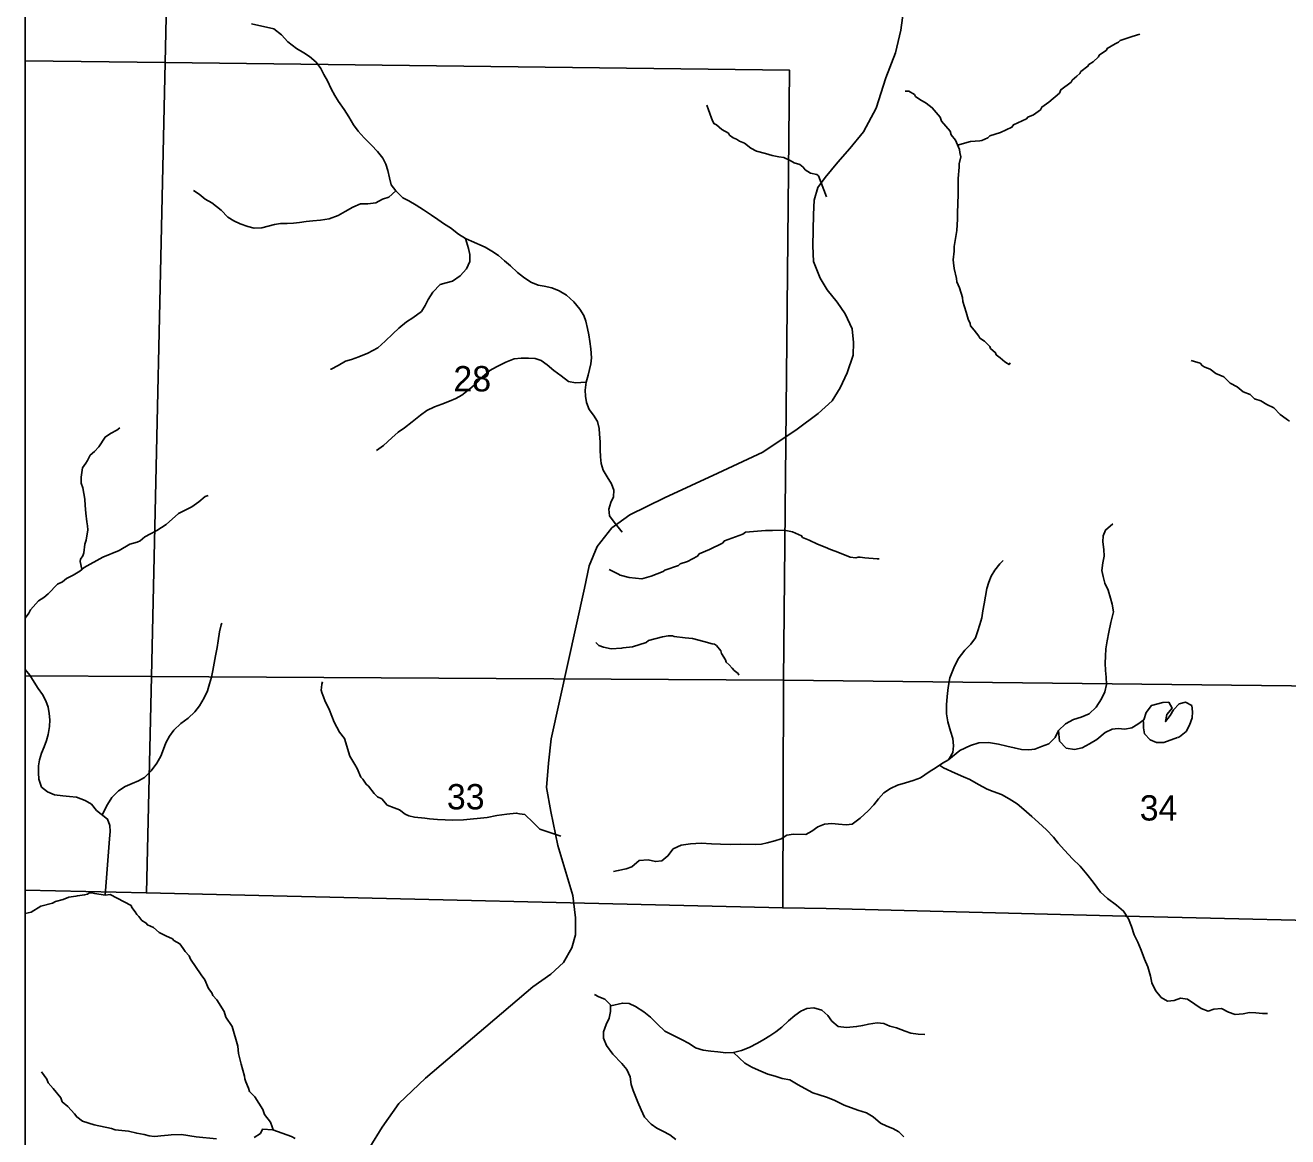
# Model space of a CAD drawing. Extents: x -10 to 158, y 8 to 33.
# Drawn here: x 2.1 to 4.186, y 15.67 to 17.507 of the extents above; entities that cross this region are included whole.
import ezdxf

# ---------------------------------------------------------------- set-up
doc = ezdxf.new("R2010")
doc.units = 0
for name, color, linetype in [('GM_X_Corporation', 7, 'Continuous'), ('GM_X_Minor_River', 7, 'Continuous'), ('GM_X_Rail_Line', 7, 'Continuous'), ('GM_X_Section_Text', 7, 'Continuous')]:
    doc.layers.add(name, color=color, linetype=linetype)

msp = doc.modelspace()

# ---------------------------------------------------------------- linework, layer by layer
at = {"layer": 'GM_X_Corporation'}
msp.add_lwpolyline([(5.7441, 17.4016), (5.3204, 17.3974), (4.9935, 17.4026), (4.6584, 17.4086), (4.4004, 17.4134), (4.4034, 17.9704), (4.4042, 18.3894), (4.0024, 18.3977), (3.4726, 18.3965), (3.3689, 18.3974), (3.3767, 18.6789), (3.3859, 18.705), (3.3893, 18.7211), (3.3872, 18.7823), (3.3779, 18.9242), (3.3711, 18.9532), (3.3709, 19.4089), (3.3147, 19.4093), (2.7824, 19.4152), (2.1, 19.4241), (2.1, 14.1), (8.9, 14.1)], dxfattribs=at)
for points in [[(2.1, 18.4216), (2.1, 17.4478), (2.3314, 17.4451), (2.3525, 18.417)], [(2.1, 17.4478), (2.1, 16.4315), (2.3088, 16.4308), (2.3314, 17.4451)], [(2.3314, 17.4451), (3.3626, 17.4323), (3.3525, 16.4245), (2.3088, 16.4308)], [(2.1, 16.4315), (2.1, 16.0777), (2.3002, 16.073), (2.3088, 16.4308)], [(2.3088, 16.4308), (3.3525, 16.4245), (3.3513, 16.0482), (2.4158, 16.0705), (2.3002, 16.073)], [(3.3525, 16.4245), (4.3887, 16.4129), (4.3853, 16.0237), (3.9176, 16.0345), (3.4233, 16.047), (3.3513, 16.0482)]]:
    msp.add_lwpolyline(points, close=True, dxfattribs=at)
at = {"layer": 'GM_X_Minor_River'}
for points in [[(3.086, 16.6691), (3.0729, 16.6858), (3.0649, 16.6963), (3.0641, 16.707), (3.0672, 16.7179), (3.0717, 16.7276), (3.0721, 16.7383), (3.0683, 16.749), (3.0614, 16.7607), (3.0546, 16.7716), (3.0512, 16.7827), (3.0501, 16.7938), (3.0497, 16.8052), (3.0498, 16.8181), (3.0487, 16.831), (3.0479, 16.8406), (3.0456, 16.8517), (3.0388, 16.8622), (3.0315, 16.8719), (3.0274, 16.8831), (3.0254, 16.8938), (3.0247, 16.9037), (3.0266, 16.9169), (3.0297, 16.9286), (3.0342, 16.9474), (3.0353, 16.9573), (3.0346, 16.9721), (3.0328, 16.984), (3.0309, 16.995), (3.029, 17.0058), (3.026, 17.0176), (3.0225, 17.0273), (3.0164, 17.0374), (3.0062, 17.0499), (2.994, 17.0606), (2.9818, 17.0678), (2.9698, 17.0728), (2.9573, 17.0755), (2.9471, 17.0774), (2.9351, 17.082), (2.9233, 17.0904), (2.9133, 17.0984), (2.9015, 17.1094), (2.8919, 17.1174), (2.8816, 17.1265), (2.8708, 17.1337), (2.8597, 17.1402), (2.8372, 17.1501), (2.8275, 17.1546), (2.8156, 17.1615), (2.8026, 17.1718), (2.7926, 17.1782), (2.7818, 17.1858), (2.7711, 17.1927), (2.7577, 17.2015), (2.7458, 17.2092), (2.7335, 17.2164), (2.7238, 17.2217), (2.7121, 17.2332), (2.7044, 17.2433), (2.7018, 17.2544), (2.6992, 17.267), (2.6957, 17.2774), (2.6908, 17.2871), (2.682, 17.2984), (2.6718, 17.3087), (2.66, 17.3209), (2.6498, 17.3319), (2.6421, 17.342), (2.6343, 17.3556), (2.6267, 17.3673), (2.6173, 17.3809), (2.6115, 17.3906), (2.6055, 17.4018), (2.5991, 17.415), (2.5934, 17.4254), (2.5884, 17.4355), (2.5808, 17.4456), (2.5697, 17.4551), (2.5601, 17.4612), (2.5482, 17.4684), (2.5337, 17.4796), (2.5231, 17.491), (2.5109, 17.5009), (2.4736, 17.5094)], [(3.6402, 17.3087), (3.6616, 17.3149), (3.6772, 17.3159), (3.6802, 17.3163), (3.6904, 17.321), (3.6933, 17.3241), (3.7111, 17.3297), (3.7299, 17.3384), (3.7325, 17.3422), (3.754, 17.3521), (3.7562, 17.3548), (3.7656, 17.3587), (3.7769, 17.3672), (3.7791, 17.3715), (3.7911, 17.3796), (3.8083, 17.3947), (3.8109, 17.4001), (3.8277, 17.4125), (3.8296, 17.4159), (3.837, 17.4229), (3.8419, 17.4272), (3.8437, 17.4302), (3.8554, 17.4391), (3.8568, 17.4418), (3.864, 17.4465), (3.8729, 17.4546), (3.874, 17.4573), (3.886, 17.4655), (3.8875, 17.4685), (3.9006, 17.4763), (3.9059, 17.4791), (3.9089, 17.4814), (3.9285, 17.4882), (3.9414, 17.4922)], [(3.5538, 17.398), (3.5596, 17.3979), (3.5692, 17.3921), (3.5704, 17.3891), (3.5777, 17.3839), (3.5884, 17.3779), (3.5984, 17.3705), (3.6112, 17.3551), (3.6136, 17.348), (3.6279, 17.3315), (3.6295, 17.3258), (3.6369, 17.3168), (3.6433, 17.3013), (3.6437, 17.2964), (3.6454, 17.2896), (3.6429, 17.2778), (3.643, 17.2724), (3.641, 17.2534), (3.6412, 17.2439), (3.6411, 17.2272), (3.6401, 17.1968), (3.6403, 17.1861), (3.6387, 17.1675), (3.6346, 17.1412), (3.6344, 17.1336), (3.6331, 17.1192), (3.6332, 17.1139), (3.6345, 17.1048), (3.6386, 17.0885), (3.6391, 17.0828), (3.6434, 17.073), (3.6482, 17.0571), (3.6491, 17.0503), (3.6544, 17.0329), (3.6576, 17.0212), (3.6608, 17.014), (3.6616, 17.0098), (3.6674, 17.0031), (3.6755, 16.9929), (3.6771, 16.9899), (3.6848, 16.9847), (3.6933, 16.9758), (3.6945, 16.9727), (3.703, 16.9656), (3.7038, 16.9622), (3.7107, 16.957), (3.7184, 16.9507), (3.7226, 16.9477), (3.7253, 16.9459), (3.7268, 16.9489)], [(3.4235, 17.2232), (3.4105, 17.2578), (3.4078, 17.26), (3.3972, 17.2621), (3.3926, 17.2651), (3.3883, 17.268), (3.3849, 17.2722), (3.3795, 17.2766), (3.3703, 17.2795), (3.3634, 17.2832), (3.3531, 17.288), (3.3451, 17.2894), (3.334, 17.2915), (3.323, 17.2951), (3.3081, 17.2987), (3.2985, 17.3035), (3.2881, 17.3117), (3.2801, 17.315), (3.2751, 17.3183), (3.2697, 17.3209), (3.2632, 17.3253), (3.2616, 17.3283), (3.2505, 17.3343), (3.2417, 17.3421), (3.2375, 17.3443), (3.2347, 17.3503), (3.2335, 17.353), (3.2311, 17.3609), (3.2287, 17.367), (3.2259, 17.3745)], [(2.7121, 17.2332), (2.7007, 17.2229), (2.6899, 17.2191), (2.6791, 17.2134), (2.6661, 17.2116), (2.6539, 17.2117), (2.6412, 17.2064), (2.6284, 17.1989), (2.6168, 17.1924), (2.6021, 17.1869), (2.5876, 17.1844), (2.575, 17.1833), (2.564, 17.1825), (2.5533, 17.181), (2.543, 17.1799), (2.5327, 17.1791), (2.5217, 17.1791), (2.5118, 17.1775), (2.5014, 17.1745), (2.4907, 17.1718), (2.4781, 17.1715), (2.4679, 17.1742), (2.4552, 17.1784), (2.4443, 17.1834), (2.4347, 17.1894), (2.4237, 17.2012), (2.4085, 17.2135), (2.3973, 17.2192), (2.3873, 17.2275), (2.3777, 17.2336)], [(2.8275, 17.1546), (2.8322, 17.1381), (2.8345, 17.1278), (2.8345, 17.1164), (2.8288, 17.1044), (2.8185, 17.0926), (2.806, 17.0839), (2.7953, 17.0809), (2.7853, 17.0782), (2.7735, 17.0657), (2.7654, 17.0535), (2.7605, 17.0434), (2.7545, 17.0337), (2.74, 17.0232), (2.7299, 17.0167), (2.717, 17.0061), (2.7072, 16.997), (2.6946, 16.9849), (2.6825, 16.9739), (2.6658, 16.965), (2.6511, 16.9587), (2.6388, 16.9546), (2.6289, 16.9519), (2.6172, 16.9443), (2.6052, 16.9387), (2.6045, 16.9387)], [(3.0266, 16.9169), (3.0091, 16.9156), (2.9974, 16.9183), (2.9852, 16.9275), (2.9734, 16.9363), (2.9623, 16.9454), (2.9523, 16.953), (2.9421, 16.956), (2.9315, 16.9568), (2.9194, 16.9568), (2.9075, 16.9553), (2.894, 16.9501), (2.8786, 16.9423), (2.8673, 16.9362), (2.8548, 16.9253), (2.8453, 16.9154), (2.8344, 16.9059), (2.8211, 16.8957), (2.8114, 16.89), (2.801, 16.8854), (2.7882, 16.8805), (2.7759, 16.876), (2.7636, 16.87), (2.753, 16.8624), (2.7394, 16.8515), (2.7265, 16.8413), (2.716, 16.8345), (2.7057, 16.8249), (2.692, 16.8125), (2.6803, 16.8038)], [(4.1886, 16.8525), (4.1851, 16.8547), (4.177, 16.8607), (4.1732, 16.8636), (4.1624, 16.8745), (4.1513, 16.88), (4.1413, 16.8859), (4.1306, 16.8892), (4.1237, 16.8963), (4.1118, 16.9011), (4.1018, 16.9093), (4.0903, 16.9151), (4.0799, 16.9256), (4.0669, 16.9311), (4.0576, 16.9382), (4.0488, 16.9415), (4.0446, 16.9441), (4.0408, 16.9482), (4.0316, 16.9511), (4.0262, 16.9529)], [(2.1935, 16.6077), (2.1905, 16.6204), (2.1912, 16.6242), (2.1949, 16.6299), (2.1967, 16.6349), (2.1987, 16.649), (2.2009, 16.6559), (2.2032, 16.673), (2.2031, 16.6795), (2.2015, 16.6863), (2.2001, 16.7007), (2.1991, 16.7132), (2.1982, 16.7238), (2.1952, 16.7424), (2.1924, 16.7503), (2.1922, 16.7598), (2.1946, 16.7751), (2.2002, 16.7831), (2.2028, 16.7877), (2.2072, 16.7962), (2.2146, 16.8024), (2.2217, 16.8101), (2.2321, 16.8262), (2.2411, 16.832), (2.2512, 16.8375), (2.2565, 16.8414)], [(2.1, 16.5272), (2.1058, 16.5354), (2.1087, 16.5408), (2.1217, 16.5555), (2.1308, 16.5609), (2.1379, 16.5671), (2.1531, 16.5829), (2.1618, 16.5872), (2.1682, 16.5927), (2.1791, 16.5981), (2.19, 16.6044), (2.1975, 16.6106), (2.2283, 16.6278), (2.2551, 16.6385), (2.2727, 16.6494), (2.2848, 16.6526), (2.2901, 16.655), (2.2976, 16.6616), (2.3171, 16.6718), (2.3329, 16.6819), (2.3531, 16.6997), (2.3753, 16.711), (2.3865, 16.7192), (2.3974, 16.7281), (2.4023, 16.7297)], [(3.0645, 16.6074), (3.0799, 16.5994), (3.0826, 16.598), (3.0978, 16.5944), (3.1184, 16.5921), (3.1342, 16.5965), (3.1538, 16.604), (3.1565, 16.6063), (3.1791, 16.6139), (3.1817, 16.6166), (3.1942, 16.6206), (3.2103, 16.6296), (3.2133, 16.6335), (3.2303, 16.6402), (3.2517, 16.6508), (3.2551, 16.655), (3.2856, 16.6658), (3.2901, 16.6692), (3.3227, 16.672), (3.3345, 16.6718), (3.3539, 16.6722), (3.3676, 16.6697), (3.3825, 16.6631), (3.3841, 16.6605), (3.3948, 16.6561), (3.4089, 16.6491), (3.4212, 16.6443), (3.4303, 16.6403), (3.438, 16.6374), (3.4479, 16.6337), (3.4628, 16.6279), (3.472, 16.6269), (3.4757, 16.6277), (3.4792, 16.6278), (3.4868, 16.6268), (3.5073, 16.6248), (3.5107, 16.6249)], [(3.6256, 16.2932), (3.6438, 16.3085), (3.6613, 16.3166), (3.6754, 16.3207), (3.6914, 16.3213), (3.7077, 16.3188), (3.7213, 16.3156), (3.7338, 16.3128), (3.7456, 16.31), (3.7577, 16.3095), (3.768, 16.3106), (3.7786, 16.3146), (3.7908, 16.3194), (3.8012, 16.3299), (3.807, 16.3413), (3.8185, 16.3522), (3.8319, 16.3592), (3.8445, 16.3636), (3.8578, 16.3688), (3.8693, 16.3801), (3.8782, 16.3937), (3.8836, 16.4054), (3.8861, 16.4175), (3.8854, 16.4296), (3.8844, 16.4403), (3.8838, 16.4528), (3.8843, 16.4642), (3.8852, 16.476), (3.8872, 16.4896), (3.89, 16.5036), (3.8936, 16.5195), (3.8976, 16.5373), (3.8958, 16.5503), (3.8929, 16.5602), (3.8889, 16.5731), (3.8837, 16.5849), (3.8808, 16.596), (3.8786, 16.6059), (3.8802, 16.6184), (3.8826, 16.6294), (3.882, 16.6404), (3.8802, 16.6533), (3.8807, 16.6628), (3.8846, 16.6726), (3.8969, 16.6827)], [(3.0718, 16.1085), (3.0797, 16.1099), (3.0927, 16.1125), (3.1022, 16.1162), (3.1141, 16.1263), (3.1289, 16.1273), (3.141, 16.1248), (3.1517, 16.1259), (3.1616, 16.1341), (3.1705, 16.1458), (3.1838, 16.1517), (3.1991, 16.1542), (3.2165, 16.1552), (3.2336, 16.1538), (3.2488, 16.1533), (3.2643, 16.1531), (3.2818, 16.1533), (3.3065, 16.1531), (3.316, 16.1537), (3.3255, 16.1555), (3.3384, 16.1592), (3.3487, 16.1625), (3.3583, 16.1684), (3.3689, 16.1698), (3.3894, 16.1696), (3.3994, 16.1752), (3.4093, 16.1819), (3.4204, 16.1864), (3.4322, 16.1874), (3.4435, 16.1865), (3.4561, 16.1856), (3.4663, 16.1866), (3.4793, 16.1964), (3.4927, 16.2084), (3.502, 16.2185), (3.5093, 16.2283), (3.5185, 16.2381), (3.5296, 16.2456), (3.5407, 16.2508), (3.554, 16.2548), (3.5669, 16.2584), (3.5791, 16.2632), (3.5933, 16.273), (3.6048, 16.2804), (3.6155, 16.2872), (3.625, 16.2927), (3.6324, 16.3052), (3.6332, 16.3158), (3.6322, 16.328), (3.6286, 16.3402), (3.6242, 16.3554), (3.6217, 16.3687), (3.6218, 16.3839), (3.6231, 16.3975), (3.6248, 16.4123), (3.6276, 16.4283), (3.6339, 16.4449), (3.6409, 16.4596), (3.652, 16.4743), (3.662, 16.4841), (3.6697, 16.4942), (3.6732, 16.5044), (3.6772, 16.5162), (3.6803, 16.5275), (3.682, 16.5389), (3.684, 16.5506), (3.6884, 16.5757), (3.692, 16.5862), (3.6955, 16.5965), (3.7017, 16.6063), (3.7098, 16.6168), (3.7155, 16.6221)], [(2.2272, 16.202), (2.2358, 16.2192), (2.243, 16.2307), (2.254, 16.2417), (2.2653, 16.2485), (2.2765, 16.2535), (2.2873, 16.258), (2.297, 16.2634), (2.308, 16.2748), (2.3176, 16.2874), (2.3241, 16.2989), (2.3283, 16.3105), (2.332, 16.321), (2.3385, 16.3322), (2.3453, 16.3418), (2.3571, 16.3528), (2.3692, 16.3615), (2.3802, 16.3721), (2.3878, 16.3821), (2.3958, 16.3952), (2.4008, 16.4068), (2.4046, 16.4184), (2.4077, 16.4297), (2.4099, 16.4402), (2.4119, 16.4527), (2.4142, 16.4648), (2.417, 16.4784), (2.4185, 16.4893), (2.4209, 16.5041), (2.4236, 16.5158), (2.4249, 16.5188)], [(3.0426, 16.4865), (3.0474, 16.4815), (3.055, 16.479), (3.068, 16.4765), (3.0851, 16.4772), (3.0877, 16.478), (3.1032, 16.4797), (3.1259, 16.4869), (3.1296, 16.49), (3.1527, 16.4961), (3.1621, 16.4978), (3.1694, 16.4975), (3.172, 16.4968), (3.1899, 16.4944), (3.2025, 16.4931), (3.2208, 16.4881), (3.2345, 16.4845), (3.2387, 16.4838), (3.2418, 16.4819), (3.2491, 16.4729), (3.25, 16.4688), (3.257, 16.4579), (3.2578, 16.4541), (3.2628, 16.4496), (3.2678, 16.4444), (3.2713, 16.4406), (3.2775, 16.4354), (3.2787, 16.4327)], [(2.2176, 16.2092), (2.2092, 16.2194), (2.1991, 16.2258), (2.1845, 16.2309), (2.1731, 16.232), (2.1622, 16.2332), (2.1482, 16.2352), (2.1366, 16.2398), (2.1266, 16.2478), (2.1225, 16.2608), (2.1217, 16.2711), (2.1221, 16.2829), (2.1236, 16.2927), (2.127, 16.3036), (2.1312, 16.3141), (2.135, 16.3246), (2.1376, 16.3348), (2.1403, 16.348), (2.1407, 16.359), (2.1396, 16.3696), (2.1377, 16.38), (2.1342, 16.3904), (2.1285, 16.4008), (2.1213, 16.4109), (2.1148, 16.4211), (2.1076, 16.4327), (2.1, 16.442)], [(2.9848, 16.1667), (2.9501, 16.1783), (2.9389, 16.1895), (2.9254, 16.2022), (2.9167, 16.2036), (2.911, 16.2047), (2.8958, 16.2033), (2.8791, 16.2007), (2.8629, 16.1974), (2.8238, 16.1934), (2.8064, 16.1931), (2.7809, 16.1943), (2.7676, 16.1952), (2.76, 16.1962), (2.7429, 16.1982), (2.7338, 16.2), (2.7276, 16.2029), (2.718, 16.2104), (2.7092, 16.2133), (2.6981, 16.218), (2.6889, 16.2281), (2.682, 16.2318), (2.6762, 16.2371), (2.6668, 16.2494), (2.6634, 16.2524), (2.6579, 16.2611), (2.6544, 16.2644), (2.6485, 16.2784), (2.6442, 16.2852), (2.636, 16.2987), (2.6272, 16.3279), (2.6194, 16.3387), (2.6104, 16.3549), (2.6024, 16.375), (2.5985, 16.3829), (2.5957, 16.3893), (2.5929, 16.3972), (2.5914, 16.3999), (2.5898, 16.404), (2.5889, 16.4082), (2.5892, 16.4124), (2.5899, 16.4181), (2.591, 16.4215)], [(3.807, 16.3413), (3.8084, 16.3238), (3.8196, 16.3123), (3.8333, 16.3099), (3.8462, 16.3124), (3.858, 16.3191), (3.8703, 16.3265), (3.8841, 16.3378), (3.8955, 16.3437), (3.9054, 16.3444), (3.9164, 16.3435), (3.9282, 16.3457), (3.9381, 16.352), (3.9477, 16.3591), (3.9516, 16.3708), (3.9605, 16.3825), (3.9795, 16.3876), (3.989, 16.3879), (3.9946, 16.378), (3.9858, 16.3678), (3.9837, 16.3561), (3.9911, 16.3659), (3.9969, 16.3757), (4.0064, 16.3854), (4.0167, 16.388), (4.0269, 16.3826), (4.0283, 16.3719), (4.0275, 16.3624), (4.0235, 16.3503), (4.0177, 16.3398), (4.0066, 16.3308), (4.0039, 16.3296)], [(4.0036, 16.3295), (3.9811, 16.3212), (3.9689, 16.3217), (3.9583, 16.326), (3.949, 16.3356), (3.9472, 16.3458), (3.9473, 16.3557), (3.9477, 16.3557)], [(3.9925, 16.3246), (3.9927, 16.3247)], [(3.6104, 16.2839), (3.6169, 16.2795), (3.6362, 16.2706), (3.6502, 16.2648), (3.6604, 16.2605), (3.6747, 16.252), (3.689, 16.2442), (3.6989, 16.2407), (3.7125, 16.2356), (3.7253, 16.2283), (3.7385, 16.2201), (3.7494, 16.2105), (3.7626, 16.1994), (3.7739, 16.1894), (3.787, 16.1771), (3.7987, 16.1648), (3.8062, 16.1552), (3.8167, 16.1434), (3.8298, 16.1292), (3.8426, 16.1173), (3.8538, 16.1039), (3.8643, 16.0905), (3.8763, 16.074), (3.8876, 16.0636), (3.9026, 16.0525), (3.9143, 16.0428), (3.9225, 16.0298), (3.9277, 16.0176), (3.9321, 16.0035), (3.9377, 15.9913), (3.9436, 15.978), (3.9491, 15.9635), (3.9543, 15.9505), (3.9587, 15.9353), (3.9612, 15.9242), (3.9672, 15.9117), (3.9765, 15.8998), (3.9867, 15.894), (3.9978, 15.895), (4.0084, 15.8991), (4.0202, 15.8974), (4.0319, 15.8893), (4.0428, 15.882), (4.0541, 15.8777), (4.0637, 15.8806), (4.0762, 15.8816), (4.0879, 15.8758), (4.0985, 15.8719), (4.1118, 15.8733), (4.1225, 15.875), (4.1331, 15.8745), (4.1441, 15.8737), (4.1521, 15.8736)], [(2.2176, 16.2092), (2.2361, 16.1949), (2.2399, 16.1841), (2.2403, 16.1742), (2.2391, 16.1625), (2.2319, 16.0693)], [(2.2751, 16.0521), (2.2402, 16.0702), (2.2319, 16.0693), (2.2148, 16.0717), (2.2094, 16.0731), (2.2064, 16.0731), (2.203, 16.0708), (2.1981, 16.0695), (2.1863, 16.0682), (2.1837, 16.0674), (2.172, 16.0661), (2.1625, 16.0621), (2.1501, 16.0589), (2.1448, 16.0562), (2.1255, 16.0509), (2.1098, 16.0408), (2.1, 16.0388)], [(2.5098, 15.6812), (2.508, 15.6861), (2.5052, 15.694), (2.4955, 15.7068), (2.4927, 15.7147), (2.4795, 15.7358), (2.4702, 15.7448), (2.4686, 15.7501), (2.4642, 15.7606), (2.4626, 15.7659), (2.4622, 15.7701), (2.4569, 15.7898), (2.4524, 15.8076), (2.4511, 15.8197), (2.4418, 15.8522), (2.4312, 15.8677), (2.4288, 15.8767), (2.4167, 15.8963), (2.4097, 15.9034), (2.4082, 15.908), (2.4027, 15.9151), (2.3968, 15.929), (2.3906, 15.9377), (2.373, 15.9636), (2.371, 15.9689), (2.3641, 15.976), (2.3606, 15.9809), (2.3551, 15.9888), (2.3455, 15.994), (2.3432, 15.997), (2.3321, 16.0017), (2.321, 16.0077), (2.3118, 16.0155), (2.3018, 16.0199), (2.2999, 16.0229), (2.2926, 16.0273), (2.2875, 16.0341), (2.2841, 16.0371), (2.2817, 16.0416), (2.2763, 16.0487), (2.2751, 16.0521)], [(3.0405, 15.9052), (3.0473, 15.9009), (3.0574, 15.8975), (3.0666, 15.8877), (3.067, 15.8771), (3.0647, 15.8657), (3.0598, 15.8556), (3.0552, 15.8433), (3.0552, 15.8326), (3.0604, 15.8207), (3.0706, 15.8066), (3.0856, 15.7909), (3.094, 15.7811), (3.0993, 15.7691), (3.1011, 15.7565), (3.1042, 15.7465), (3.1119, 15.7273), (3.1175, 15.7145), (3.1232, 15.7025), (3.1338, 15.6908), (3.1434, 15.684), (3.1531, 15.6791), (3.1647, 15.6733), (3.1747, 15.6654)], [(3.0673, 15.8861), (3.0865, 15.8908), (3.0978, 15.8904), (3.1079, 15.8851), (3.1217, 15.8766), (3.1331, 15.8675), (3.1445, 15.8561), (3.1567, 15.8446), (3.1708, 15.8373), (3.1843, 15.8307), (3.197, 15.8238), (3.2074, 15.817), (3.2201, 15.8131), (3.2326, 15.8115), (3.2444, 15.81), (3.2576, 15.8088), (3.2702, 15.8094), (3.2832, 15.8124), (3.2959, 15.8173), (3.3095, 15.8248), (3.3203, 15.8305), (3.33, 15.8366), (3.3398, 15.8431), (3.3499, 15.8511), (3.3609, 15.8613), (3.3715, 15.8701), (3.3812, 15.8773), (3.3913, 15.8819), (3.4027, 15.883), (3.4159, 15.8792), (3.4258, 15.8704), (3.4327, 15.8607), (3.443, 15.852), (3.4567, 15.8507), (3.4734, 15.852), (3.4834, 15.854), (3.493, 15.8559), (3.5075, 15.8584), (3.5181, 15.8569), (3.5282, 15.8528), (3.5395, 15.8497), (3.5534, 15.8443), (3.5631, 15.8413), (3.5752, 15.8397), (3.5862, 15.8389)], [(3.2702, 15.8094), (3.2889, 15.7913), (3.3001, 15.7848), (3.3113, 15.7799), (3.3267, 15.7736), (3.3391, 15.7698), (3.3504, 15.7663), (3.3628, 15.764), (3.377, 15.7555), (3.3878, 15.7494), (3.4008, 15.7425), (3.4114, 15.7391), (3.4234, 15.7353), (3.4365, 15.7302), (3.4526, 15.7221), (3.4755, 15.714), (3.4897, 15.7097), (3.5005, 15.7029), (3.5127, 15.6922), (3.5235, 15.6872), (3.5333, 15.6835), (3.543, 15.6782), (3.5514, 15.6699)], [(2.4157, 15.6664), (2.3823, 15.67), (2.3579, 15.6738), (2.3412, 15.6732), (2.3363, 15.6727), (2.3238, 15.6714), (2.3189, 15.671), (2.3128, 15.6705), (2.3048, 15.6715), (2.2964, 15.6736), (2.2842, 15.6757), (2.2705, 15.6789), (2.2488, 15.6816), (2.2427, 15.6838), (2.2141, 15.6898), (2.1943, 15.6956), (2.1851, 15.7027), (2.1816, 15.7079), (2.1703, 15.7199), (2.1611, 15.7277), (2.1587, 15.7342), (2.1459, 15.7499), (2.1378, 15.7589), (2.1358, 15.765), (2.1268, 15.777)], [(2.5459, 15.6673), (2.5398, 15.6703), (2.5089, 15.6815), (2.4918, 15.6824), (2.4888, 15.6755), (2.4783, 15.6685)]]:
    msp.add_lwpolyline(points, dxfattribs=at)
at = {"layer": 'GM_X_Rail_Line'}
msp.add_lwpolyline([(3.551, 17.5313), (3.5465, 17.4988), (3.5377, 17.4612), (3.5214, 17.4198), (3.5056, 17.3699), (3.485, 17.3308), (3.4624, 17.3032), (3.4425, 17.2803), (3.4217, 17.2552), (3.4093, 17.2389), (3.4034, 17.2175), (3.4019, 17.1939), (3.4012, 17.1422), (3.4019, 17.1164), (3.413, 17.089), (3.4248, 17.0698), (3.441, 17.0492), (3.4543, 17.03), (3.4661, 17.0049), (3.4683, 16.9827), (3.4676, 16.9613), (3.458, 16.9325), (3.4462, 16.9074), (3.4329, 16.886), (3.41, 16.8653), (3.3753, 16.8395), (3.3185, 16.8011), (3.244, 16.7664), (3.1562, 16.7257), (3.0986, 16.6977), (3.0691, 16.6763), (3.0447, 16.6452), (3.0314, 16.6135), (3.0241, 16.5766), (2.9687, 16.3277), (2.9643, 16.2871), (2.9613, 16.2472), (2.968, 16.2073), (2.9798, 16.1512), (3.0044, 16.0688), (3.009, 16.0315), (3.0088, 16.0036), (3.0027, 15.9822), (2.9894, 15.9578), (2.968, 15.9388), (2.9384, 15.9179), (2.7613, 15.7665), (2.717, 15.7251), (2.6897, 15.686), (2.6691, 15.6527)], dxfattribs=at)

# ---------------------------------------------------------------- texts
at = {"layer": 'GM_X_Section_Text'}
for s, p in [('28', (2.8073, 16.9017)), ('33', (2.7965, 16.2109)), ('34', (3.9411, 16.1925))]:
    msp.add_text(s, height=0.04186, rotation=0, dxfattribs=at).set_placement(p)

doc.saveas('drawing.dxf')
